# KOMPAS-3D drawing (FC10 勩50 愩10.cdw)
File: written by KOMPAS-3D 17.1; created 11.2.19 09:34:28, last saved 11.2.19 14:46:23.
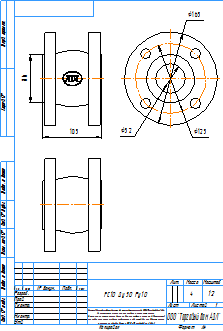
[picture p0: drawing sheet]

Sheet 1: A4, portrait

Title block, sheet 1: name: FC10 Ду50 Ру10; mass: 4; sheets: 1; sheet format: A4; stored path: \\adlc.lan\data\АДЛ_ПКД\3D-модели\ADL production\Гибкие вставки серии FC\FC10\KOMPAS 2D\FC10 Ду50 Ру10.cdw

Views: Вид 1
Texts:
  kka
  adl
  Рама для чертежей
  Лит-Масса-Масштаб
  Материал-Предприятие
  Масштаб
  Изм.
  Лист
  № докум.
  Подп.
  Дата
  Лит.
  Разраб.
  Пров.
  Т.контр.
  Листов
  Внимание! Данный продукт является объектом авторского права ООО «Торговый Дом АДЛ».
  Запрещается изменение, копирование, распространение
  (в том числе путем копирования на другие сайты и ресурсы в Интернете)
  или любое иное использование информации и объектов без предварительного
  согласия правообладателя (ООО «Торговый Дом АДЛ»).
  Н.контр.
  Утв.
  ООО "Торговый дом АДЛ"
  Изменение
  Номер документа
  Подпись
  Обозначение документа
  Наименование изделия
  Масса изделия по ГОСТ 2.109-73
  Порядковый номер листа
  Общее количество листов в документе
  Характер работы, выполненной лицом, подписавшим документ
  Наименование или индекс предприятия, выпускающего документ
  Инв. № подл.
  Подп. и дата
  Взам. инв. №
  Инв. № дубл.
  Инвентарный номер подлинника по ГОСТ 2.501-68
  Подпись принявшего подлинник в отдел технической документации
  Инвентарный номер подлинника, взамен которого выпущен данный подлинник
  Инвентарный номер дубликата по ГОСТ 2.502-68
  Подпись принявшего дубликат в отдел технической документации
  Справ. №
  Перв. примен.
  Обозначение документа, взамен или на основании которого выпущен данный документ
  Обозначение документа, в котором впервые записан данный документ
  Подпись лица, копировавшего чертеж
  Обозначение формата листа
  !Рама для чертежа
Dimensions and other numbers on the sheet: 105; 86; 52; 125; 165; 1:2; 1; 4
